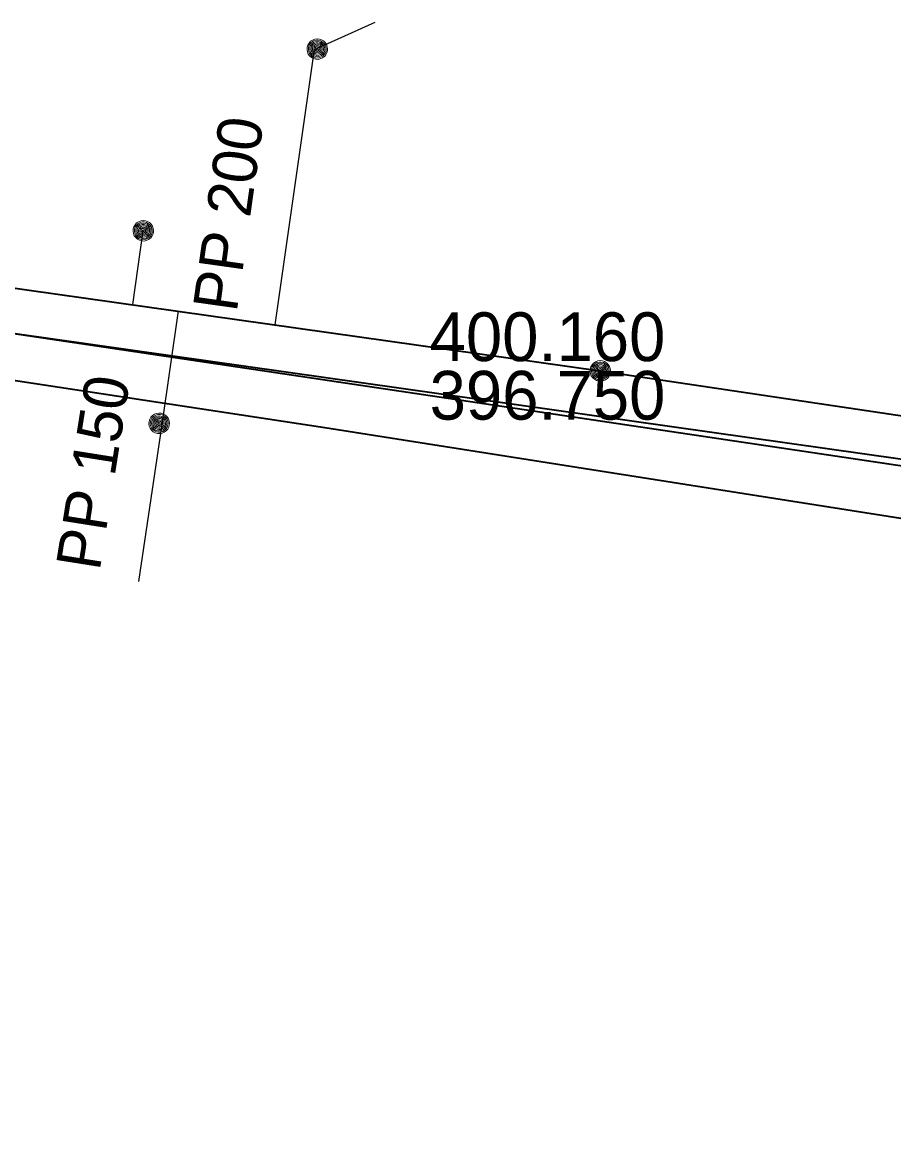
# Model space of a CAD drawing. Extents: x -866761 to -866592, y -1013996 to -1013877.
# Drawn here: x -866722.08 to -866702.42, y -1013979.36 to -1013954.44 of the extents above; entities that cross this region are included whole.
import ezdxf

# ---------------------------------------------------------------- set-up
doc = ezdxf.new("R2010")
doc.units = 0
doc.header["$LTSCALE"] = 0.44
for name, color, linetype, lineweight in [('1', 7, 'Continuous', 35), ('21', 7, 'Continuous', 35), ('23', 7, 'Continuous', 25), ('25', 7, 'Continuous', 13), ('32', 7, 'Continuous', 13)]:
    doc.layers.add(name, color=color, linetype=linetype, lineweight=lineweight)

msp = doc.modelspace()

# ---------------------------------------------------------------- linework, layer by layer
at = {"layer": '1'}
msp.add_line((-866612.967, -1013977.763), (-866734.931, -1013959.586), dxfattribs=at)
for points in [[(-866612.815, -1013977.108), (-866621.035, -1013976.325), (-866621.378, -1013976.297), (-866626.243, -1013975.519), (-866632.94, -1013974.51), (-866645.03, -1013972.86), (-866647.305, -1013972.501), (-866654.48, -1013971.31), (-866668.882, -1013969.171), (-866678.229, -1013967.78), (-866685.446, -1013966.718), (-866689.8, -1013966.06), (-866697.865, -1013964.927), (-866723.097, -1013961.352), (-866726.923, -1013960.77), (-866727.214, -1013960.734), (-866737.38, -1013959.64), (-866746.09, -1013958.48), (-866747.84, -1013958.25), (-866748.13, -1013958.99), (-866750.15, -1013958.69)], [(-866613.338, -1013979.363), (-866624.951, -1013977.802), (-866715.256, -1013963.593), (-866735.102, -1013960.577)]]:
    msp.add_lwpolyline(points, dxfattribs=at)
at = {"layer": '21'}
for p, q in [((-866743.07, -1013957.51), (-866709.04, -1013962.31)), ((-866709.04, -1013962.31), (-866647.459, -1013971.5))]:
    msp.add_line(p, q, dxfattribs=at)
at = {"layer": '23'}
msp.add_line((-866719.586, -1013960.812), (-866719.35, -1013959.15), dxfattribs=at)
for points in [[(-866716.372, -1013961.268), (-866715.489, -1013955.06), (-866714.123, -1013954.443)], [(-866718.565, -1013960.957), (-866718.93, -1013963.52), (-866719.459, -1013967.058)]]:
    msp.add_lwpolyline(points, dxfattribs=at)
at = {"layer": '25'}
for points in [[(-866719.119, -1013959.15), (-866719.125, -1013959.098), (-866719.142, -1013959.048), (-866719.171, -1013959.004), (-866719.208, -1013958.967), (-866719.253, -1013958.94), (-866719.303, -1013958.923), (-866719.356, -1013958.919), (-866719.407, -1013958.926), (-866719.456, -1013958.945), (-866719.5, -1013958.974), (-866719.536, -1013959.013), (-866719.562, -1013959.058), (-866719.578, -1013959.109), (-866719.581, -1013959.161), (-866719.573, -1013959.213), (-866719.553, -1013959.262), (-866719.522, -1013959.305), (-866719.483, -1013959.339), (-866719.437, -1013959.365), (-866719.386, -1013959.379), (-866719.333, -1013959.381), (-866719.282, -1013959.371), (-866719.233, -1013959.35), (-866719.191, -1013959.319), (-866719.157, -1013959.278), (-866719.133, -1013959.232), (-866719.12, -1013959.181)], [(-866719.149, -1013959.15), (-866719.155, -1013959.101), (-866719.172, -1013959.055), (-866719.2, -1013959.015), (-866719.237, -1013958.983), (-866719.281, -1013958.961), (-866719.329, -1013958.95), (-866719.378, -1013958.95), (-866719.424, -1013958.963), (-866719.468, -1013958.987), (-866719.504, -1013959.02), (-866719.531, -1013959.061), (-866719.547, -1013959.108), (-866719.551, -1013959.157), (-866719.544, -1013959.205), (-866719.525, -1013959.25), (-866719.495, -1013959.29), (-866719.456, -1013959.321), (-866719.413, -1013959.341), (-866719.365, -1013959.351), (-866719.316, -1013959.349), (-866719.269, -1013959.334), (-866719.226, -1013959.309), (-866719.191, -1013959.275), (-866719.166, -1013959.233), (-866719.152, -1013959.186)], [(-866719.179, -1013959.15), (-866719.184, -1013959.105), (-866719.201, -1013959.063), (-866719.23, -1013959.028), (-866719.266, -1013959.001), (-866719.308, -1013958.984), (-866719.353, -1013958.979), (-866719.397, -1013958.985), (-866719.439, -1013959.004), (-866719.473, -1013959.032), (-866719.5, -1013959.069), (-866719.517, -1013959.111), (-866719.521, -1013959.156), (-866719.514, -1013959.201), (-866719.495, -1013959.242), (-866719.466, -1013959.276), (-866719.429, -1013959.302), (-866719.386, -1013959.318), (-866719.341, -1013959.321), (-866719.296, -1013959.313), (-866719.255, -1013959.293), (-866719.222, -1013959.264), (-866719.196, -1013959.226), (-866719.182, -1013959.183)], [(-866719.209, -1013959.15), (-866719.213, -1013959.109), (-866719.232, -1013959.072), (-866719.259, -1013959.041), (-866719.294, -1013959.02), (-866719.334, -1013959.009), (-866719.375, -1013959.011), (-866719.414, -1013959.024), (-866719.448, -1013959.048), (-866719.473, -1013959.08), (-866719.488, -1013959.118), (-866719.49, -1013959.159), (-866719.483, -1013959.199), (-866719.463, -1013959.235), (-866719.434, -1013959.264), (-866719.397, -1013959.283), (-866719.357, -1013959.291), (-866719.316, -1013959.287), (-866719.277, -1013959.272), (-866719.245, -1013959.246), (-866719.223, -1013959.212), (-866719.21, -1013959.173)], [(-866719.239, -1013959.15), (-866719.244, -1013959.114), (-866719.262, -1013959.082), (-866719.288, -1013959.057), (-866719.321, -1013959.042), (-866719.358, -1013959.039), (-866719.392, -1013959.047), (-866719.424, -1013959.067), (-866719.446, -1013959.095), (-866719.46, -1013959.129), (-866719.46, -1013959.166), (-866719.449, -1013959.201), (-866719.428, -1013959.23), (-866719.397, -1013959.251), (-866719.363, -1013959.261), (-866719.326, -1013959.259), (-866719.292, -1013959.245), (-866719.265, -1013959.222), (-866719.245, -1013959.19), (-866719.239, -1013959.155)], [(-866719.269, -1013959.15), (-866719.274, -1013959.119), (-866719.291, -1013959.093), (-866719.316, -1013959.076), (-866719.347, -1013959.069), (-866719.378, -1013959.073), (-866719.405, -1013959.09), (-866719.423, -1013959.114), (-866719.431, -1013959.145), (-866719.427, -1013959.175), (-866719.412, -1013959.203), (-866719.387, -1013959.222), (-866719.358, -1013959.231), (-866719.326, -1013959.228), (-866719.299, -1013959.214), (-866719.279, -1013959.19), (-866719.269, -1013959.161)], [(-866719.299, -1013959.15), (-866719.304, -1013959.126), (-866719.321, -1013959.108), (-866719.343, -1013959.099), (-866719.368, -1013959.102), (-866719.389, -1013959.116), (-866719.4, -1013959.138), (-866719.4, -1013959.163), (-866719.387, -1013959.184), (-866719.368, -1013959.198), (-866719.343, -1013959.201), (-866719.32, -1013959.192), (-866719.304, -1013959.174)], [(-866719.329, -1013959.15), (-866719.334, -1013959.135), (-866719.348, -1013959.129), (-866719.364, -1013959.133), (-866719.37, -1013959.147), (-866719.367, -1013959.162), (-866719.353, -1013959.171), (-866719.338, -1013959.168), (-866719.329, -1013959.156)]]:
    msp.add_lwpolyline(points, close=True, dxfattribs=at)
at = {"layer": '32'}
for points in [[(-866715.194, -1013955.052), (-866715.2, -1013955), (-866715.217, -1013954.95), (-866715.246, -1013954.906), (-866715.283, -1013954.869), (-866715.328, -1013954.842), (-866715.378, -1013954.825), (-866715.431, -1013954.821), (-866715.483, -1013954.828), (-866715.532, -1013954.847), (-866715.575, -1013954.876), (-866715.611, -1013954.915), (-866715.637, -1013954.96), (-866715.653, -1013955.011), (-866715.656, -1013955.063), (-866715.648, -1013955.115), (-866715.628, -1013955.164), (-866715.597, -1013955.207), (-866715.558, -1013955.241), (-866715.512, -1013955.267), (-866715.461, -1013955.281), (-866715.408, -1013955.283), (-866715.357, -1013955.273), (-866715.309, -1013955.252), (-866715.266, -1013955.221), (-866715.232, -1013955.18), (-866715.208, -1013955.134), (-866715.196, -1013955.083)], [(-866715.224, -1013955.052), (-866715.23, -1013955.003), (-866715.247, -1013954.957), (-866715.275, -1013954.917), (-866715.312, -1013954.885), (-866715.356, -1013954.863), (-866715.404, -1013954.852), (-866715.453, -1013954.852), (-866715.5, -1013954.865), (-866715.543, -1013954.889), (-866715.579, -1013954.922), (-866715.606, -1013954.963), (-866715.622, -1013955.01), (-866715.626, -1013955.059), (-866715.619, -1013955.107), (-866715.6, -1013955.152), (-866715.57, -1013955.192), (-866715.532, -1013955.223), (-866715.488, -1013955.243), (-866715.44, -1013955.253), (-866715.391, -1013955.251), (-866715.344, -1013955.236), (-866715.301, -1013955.211), (-866715.267, -1013955.177), (-866715.241, -1013955.135), (-866715.227, -1013955.088)], [(-866715.254, -1013955.052), (-866715.26, -1013955.007), (-866715.277, -1013954.965), (-866715.305, -1013954.93), (-866715.341, -1013954.903), (-866715.383, -1013954.886), (-866715.428, -1013954.881), (-866715.473, -1013954.887), (-866715.514, -1013954.906), (-866715.549, -1013954.934), (-866715.576, -1013954.971), (-866715.592, -1013955.013), (-866715.596, -1013955.058), (-866715.589, -1013955.103), (-866715.57, -1013955.144), (-866715.541, -1013955.178), (-866715.504, -1013955.204), (-866715.461, -1013955.22), (-866715.416, -1013955.223), (-866715.371, -1013955.215), (-866715.331, -1013955.195), (-866715.297, -1013955.166), (-866715.271, -1013955.128), (-866715.257, -1013955.085)], [(-866715.284, -1013955.052), (-866715.289, -1013955.011), (-866715.307, -1013954.974), (-866715.334, -1013954.943), (-866715.369, -1013954.922), (-866715.409, -1013954.911), (-866715.45, -1013954.913), (-866715.489, -1013954.926), (-866715.523, -1013954.95), (-866715.548, -1013954.982), (-866715.563, -1013955.02), (-866715.566, -1013955.061), (-866715.558, -1013955.101), (-866715.538, -1013955.137), (-866715.509, -1013955.166), (-866715.472, -1013955.185), (-866715.432, -1013955.193), (-866715.391, -1013955.189), (-866715.353, -1013955.174), (-866715.321, -1013955.148), (-866715.298, -1013955.114), (-866715.285, -1013955.075)], [(-866715.314, -1013955.052), (-866715.319, -1013955.016), (-866715.337, -1013954.984), (-866715.363, -1013954.959), (-866715.397, -1013954.944), (-866715.433, -1013954.941), (-866715.468, -1013954.949), (-866715.499, -1013954.969), (-866715.522, -1013954.997), (-866715.535, -1013955.031), (-866715.535, -1013955.068), (-866715.524, -1013955.103), (-866715.503, -1013955.132), (-866715.473, -1013955.153), (-866715.438, -1013955.163), (-866715.401, -1013955.161), (-866715.367, -1013955.147), (-866715.34, -1013955.124), (-866715.321, -1013955.092), (-866715.314, -1013955.057)], [(-866715.344, -1013955.052), (-866715.349, -1013955.021), (-866715.366, -1013954.995), (-866715.392, -1013954.978), (-866715.422, -1013954.971), (-866715.453, -1013954.975), (-866715.48, -1013954.992), (-866715.498, -1013955.016), (-866715.506, -1013955.047), (-866715.502, -1013955.077), (-866715.487, -1013955.105), (-866715.463, -1013955.124), (-866715.433, -1013955.133), (-866715.402, -1013955.13), (-866715.374, -1013955.116), (-866715.354, -1013955.092), (-866715.344, -1013955.063)], [(-866715.374, -1013955.052), (-866715.379, -1013955.028), (-866715.396, -1013955.01), (-866715.419, -1013955.001), (-866715.443, -1013955.004), (-866715.464, -1013955.018), (-866715.475, -1013955.04), (-866715.475, -1013955.065), (-866715.463, -1013955.086), (-866715.443, -1013955.1), (-866715.418, -1013955.103), (-866715.395, -1013955.094), (-866715.379, -1013955.076)], [(-866715.404, -1013955.052), (-866715.409, -1013955.037), (-866715.424, -1013955.031), (-866715.439, -1013955.035), (-866715.446, -1013955.049), (-866715.442, -1013955.064), (-866715.429, -1013955.073), (-866715.414, -1013955.07), (-866715.404, -1013955.058)], [(-866708.809, -1013962.31), (-866708.815, -1013962.258), (-866708.832, -1013962.208), (-866708.861, -1013962.164), (-866708.898, -1013962.127), (-866708.943, -1013962.1), (-866708.993, -1013962.083), (-866709.046, -1013962.079), (-866709.098, -1013962.086), (-866709.147, -1013962.105), (-866709.19, -1013962.134), (-866709.226, -1013962.173), (-866709.252, -1013962.218), (-866709.268, -1013962.269), (-866709.271, -1013962.321), (-866709.263, -1013962.373), (-866709.243, -1013962.422), (-866709.212, -1013962.465), (-866709.173, -1013962.499), (-866709.127, -1013962.525), (-866709.076, -1013962.539), (-866709.023, -1013962.541), (-866708.972, -1013962.531), (-866708.924, -1013962.51), (-866708.881, -1013962.479), (-866708.847, -1013962.438), (-866708.823, -1013962.392), (-866708.811, -1013962.341)], [(-866708.839, -1013962.31), (-866708.845, -1013962.261), (-866708.862, -1013962.215), (-866708.89, -1013962.175), (-866708.927, -1013962.143), (-866708.971, -1013962.121), (-866709.019, -1013962.11), (-866709.068, -1013962.11), (-866709.115, -1013962.123), (-866709.158, -1013962.147), (-866709.194, -1013962.18), (-866709.221, -1013962.221), (-866709.237, -1013962.268), (-866709.241, -1013962.317), (-866709.234, -1013962.365), (-866709.215, -1013962.41), (-866709.185, -1013962.45), (-866709.147, -1013962.481), (-866709.103, -1013962.501), (-866709.055, -1013962.511), (-866709.006, -1013962.509), (-866708.959, -1013962.494), (-866708.916, -1013962.469), (-866708.882, -1013962.435), (-866708.856, -1013962.393), (-866708.842, -1013962.346)], [(-866708.869, -1013962.31), (-866708.875, -1013962.265), (-866708.892, -1013962.223), (-866708.92, -1013962.188), (-866708.956, -1013962.161), (-866708.998, -1013962.144), (-866709.043, -1013962.139), (-866709.088, -1013962.145), (-866709.129, -1013962.164), (-866709.164, -1013962.192), (-866709.191, -1013962.229), (-866709.207, -1013962.271), (-866709.211, -1013962.316), (-866709.204, -1013962.361), (-866709.185, -1013962.402), (-866709.156, -1013962.436), (-866709.119, -1013962.462), (-866709.076, -1013962.478), (-866709.031, -1013962.481), (-866708.986, -1013962.473), (-866708.946, -1013962.453), (-866708.912, -1013962.424), (-866708.886, -1013962.386), (-866708.872, -1013962.343)], [(-866708.899, -1013962.31), (-866708.904, -1013962.269), (-866708.922, -1013962.232), (-866708.949, -1013962.201), (-866708.984, -1013962.18), (-866709.024, -1013962.169), (-866709.065, -1013962.171), (-866709.104, -1013962.184), (-866709.138, -1013962.208), (-866709.163, -1013962.24), (-866709.178, -1013962.278), (-866709.181, -1013962.319), (-866709.173, -1013962.359), (-866709.153, -1013962.395), (-866709.124, -1013962.424), (-866709.087, -1013962.443), (-866709.047, -1013962.451), (-866709.006, -1013962.447), (-866708.968, -1013962.432), (-866708.936, -1013962.406), (-866708.913, -1013962.372), (-866708.9, -1013962.333)], [(-866708.929, -1013962.31), (-866708.934, -1013962.274), (-866708.952, -1013962.242), (-866708.978, -1013962.217), (-866709.012, -1013962.202), (-866709.048, -1013962.199), (-866709.083, -1013962.207), (-866709.114, -1013962.227), (-866709.137, -1013962.255), (-866709.15, -1013962.289), (-866709.15, -1013962.326), (-866709.139, -1013962.361), (-866709.118, -1013962.39), (-866709.088, -1013962.411), (-866709.053, -1013962.421), (-866709.016, -1013962.419), (-866708.982, -1013962.405), (-866708.955, -1013962.382), (-866708.936, -1013962.35), (-866708.929, -1013962.315)], [(-866708.959, -1013962.31), (-866708.964, -1013962.279), (-866708.981, -1013962.253), (-866709.007, -1013962.236), (-866709.037, -1013962.229), (-866709.068, -1013962.233), (-866709.095, -1013962.25), (-866709.113, -1013962.274), (-866709.121, -1013962.305), (-866709.117, -1013962.335), (-866709.102, -1013962.363), (-866709.078, -1013962.382), (-866709.048, -1013962.391), (-866709.017, -1013962.388), (-866708.989, -1013962.374), (-866708.969, -1013962.35), (-866708.959, -1013962.321)], [(-866708.989, -1013962.31), (-866708.994, -1013962.286), (-866709.011, -1013962.268), (-866709.034, -1013962.259), (-866709.058, -1013962.262), (-866709.079, -1013962.276), (-866709.09, -1013962.298), (-866709.09, -1013962.323), (-866709.078, -1013962.344), (-866709.058, -1013962.358), (-866709.033, -1013962.361), (-866709.01, -1013962.352), (-866708.994, -1013962.334)], [(-866709.019, -1013962.31), (-866709.024, -1013962.295), (-866709.039, -1013962.289), (-866709.054, -1013962.293), (-866709.061, -1013962.307), (-866709.057, -1013962.322), (-866709.044, -1013962.331), (-866709.029, -1013962.328), (-866709.019, -1013962.316)], [(-866718.762, -1013963.494), (-866718.768, -1013963.442), (-866718.785, -1013963.392), (-866718.814, -1013963.348), (-866718.851, -1013963.311), (-866718.896, -1013963.284), (-866718.946, -1013963.267), (-866718.999, -1013963.263), (-866719.051, -1013963.27), (-866719.1, -1013963.289), (-866719.143, -1013963.318), (-866719.179, -1013963.357), (-866719.205, -1013963.402), (-866719.221, -1013963.453), (-866719.224, -1013963.505), (-866719.216, -1013963.557), (-866719.196, -1013963.606), (-866719.165, -1013963.649), (-866719.126, -1013963.683), (-866719.08, -1013963.709), (-866719.029, -1013963.723), (-866718.976, -1013963.725), (-866718.925, -1013963.715), (-866718.877, -1013963.694), (-866718.834, -1013963.663), (-866718.8, -1013963.622), (-866718.776, -1013963.576), (-866718.764, -1013963.525)], [(-866718.792, -1013963.494), (-866718.798, -1013963.445), (-866718.815, -1013963.399), (-866718.843, -1013963.359), (-866718.88, -1013963.327), (-866718.924, -1013963.305), (-866718.972, -1013963.294), (-866719.021, -1013963.294), (-866719.068, -1013963.307), (-866719.111, -1013963.331), (-866719.147, -1013963.364), (-866719.174, -1013963.405), (-866719.19, -1013963.452), (-866719.194, -1013963.501), (-866719.187, -1013963.549), (-866719.168, -1013963.594), (-866719.138, -1013963.634), (-866719.1, -1013963.665), (-866719.056, -1013963.685), (-866719.008, -1013963.695), (-866718.959, -1013963.693), (-866718.912, -1013963.678), (-866718.869, -1013963.653), (-866718.835, -1013963.619), (-866718.809, -1013963.577), (-866718.795, -1013963.53)], [(-866718.822, -1013963.494), (-866718.828, -1013963.449), (-866718.845, -1013963.407), (-866718.873, -1013963.372), (-866718.909, -1013963.345), (-866718.951, -1013963.328), (-866718.996, -1013963.323), (-866719.041, -1013963.329), (-866719.082, -1013963.348), (-866719.117, -1013963.376), (-866719.144, -1013963.413), (-866719.16, -1013963.455), (-866719.164, -1013963.5), (-866719.157, -1013963.545), (-866719.138, -1013963.586), (-866719.109, -1013963.62), (-866719.072, -1013963.646), (-866719.029, -1013963.662), (-866718.984, -1013963.665), (-866718.939, -1013963.657), (-866718.899, -1013963.637), (-866718.865, -1013963.608), (-866718.839, -1013963.57), (-866718.825, -1013963.527)], [(-866718.852, -1013963.494), (-866718.857, -1013963.453), (-866718.875, -1013963.416), (-866718.902, -1013963.385), (-866718.937, -1013963.364), (-866718.977, -1013963.353), (-866719.018, -1013963.355), (-866719.057, -1013963.368), (-866719.091, -1013963.392), (-866719.116, -1013963.424), (-866719.131, -1013963.462), (-866719.134, -1013963.503), (-866719.126, -1013963.543), (-866719.106, -1013963.579), (-866719.077, -1013963.608), (-866719.04, -1013963.627), (-866719, -1013963.635), (-866718.959, -1013963.631), (-866718.921, -1013963.616), (-866718.889, -1013963.59), (-866718.866, -1013963.556), (-866718.853, -1013963.517)], [(-866718.882, -1013963.494), (-866718.887, -1013963.458), (-866718.905, -1013963.426), (-866718.931, -1013963.401), (-866718.965, -1013963.386), (-866719.001, -1013963.383), (-866719.036, -1013963.391), (-866719.067, -1013963.411), (-866719.09, -1013963.439), (-866719.103, -1013963.473), (-866719.103, -1013963.51), (-866719.092, -1013963.545), (-866719.071, -1013963.574), (-866719.041, -1013963.595), (-866719.006, -1013963.605), (-866718.969, -1013963.603), (-866718.935, -1013963.589), (-866718.908, -1013963.566), (-866718.889, -1013963.534), (-866718.882, -1013963.499)], [(-866718.912, -1013963.494), (-866718.917, -1013963.463), (-866718.934, -1013963.437), (-866718.96, -1013963.42), (-866718.99, -1013963.413), (-866719.021, -1013963.417), (-866719.048, -1013963.434), (-866719.066, -1013963.458), (-866719.074, -1013963.489), (-866719.07, -1013963.519), (-866719.055, -1013963.547), (-866719.031, -1013963.566), (-866719.001, -1013963.575), (-866718.97, -1013963.572), (-866718.942, -1013963.558), (-866718.922, -1013963.534), (-866718.912, -1013963.505)], [(-866718.942, -1013963.494), (-866718.947, -1013963.47), (-866718.964, -1013963.452), (-866718.987, -1013963.443), (-866719.011, -1013963.446), (-866719.032, -1013963.46), (-866719.043, -1013963.482), (-866719.043, -1013963.507), (-866719.031, -1013963.528), (-866719.011, -1013963.542), (-866718.986, -1013963.545), (-866718.963, -1013963.536), (-866718.947, -1013963.518)], [(-866718.972, -1013963.494), (-866718.977, -1013963.479), (-866718.992, -1013963.473), (-866719.007, -1013963.477), (-866719.014, -1013963.491), (-866719.01, -1013963.506), (-866718.997, -1013963.515), (-866718.982, -1013963.512), (-866718.972, -1013963.5)]]:
    msp.add_lwpolyline(points, close=True, dxfattribs=at)

# ---------------------------------------------------------------- texts
at = {"layer": '23'}
for s, rotation, p in [('PP 200', 82, (-866717.244, -1013961.007)), ('PP 150', 81, (-866720.336, -1013966.841))]:
    msp.add_text(s, height=1, rotation=rotation, dxfattribs=at).set_placement(p)
at = {"layer": '25'}
for s, p in [('400.160 ', (-866712.89, -1013962.09)), ('396.750 ', (-866712.89, -1013963.41))]:
    msp.add_text(s, height=1.1, dxfattribs=at).set_placement(p)

doc.saveas('drawing.dxf')
